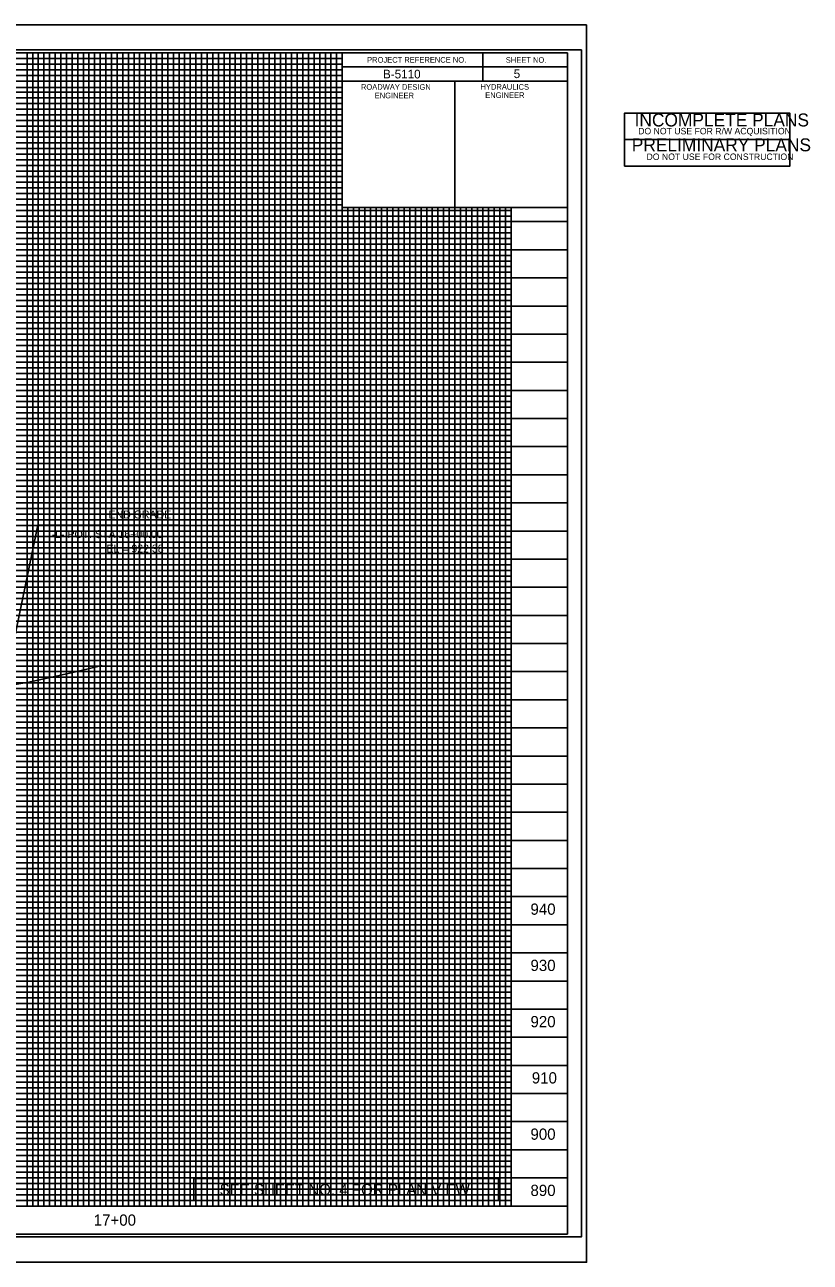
# Model space of a CAD drawing. Extents: x 573624 to 575507, y -53727 to -52273.
# Drawn here: x 574809 to 575507, y -53373 to -52273 of the extents above; entities that cross this region are included whole.
import ezdxf

# ---------------------------------------------------------------- set-up
doc = ezdxf.new("R2010")
doc.units = 0
for name, color, linetype in [('Exist Profile Cell', 7, 'Continuous'), ('Exist Vertical Profile Ground Line', 7, 'Continuous'), ('Exist Vertical Profile Horizontal Axis Label Major', 7, 'Continuous'), ('Exist Vertical Profile Vertical Axis Label', 7, 'Continuous'), ('Prop DSN Text', 7, 'Continuous'), ('Prop Grid Mask', 7, 'Continuous'), ('Prop VPI Label', 7, 'Continuous'), ('Sheet Cutting Line CELL', 7, 'Continuous'), ('Sheet Data Field CELL', 7, 'Continuous'), ('Sheet DOT Grid CELL', 7, 'Continuous'), ('Sheet Layout Profile Border', 7, 'Continuous'), ('Sheet Plot Border Inside CELL', 7, 'Continuous'), ('Sheet Plot Border Outside CELL', 7, 'Continuous'), ('Sheet Profile CELL', 7, 'Continuous'), ('Sheet Profile Grid Major CELL', 7, 'Continuous'), ('Sheet Profile Grid Middle CELL', 7, 'Continuous'), ('Sheet Profile Grid Minor CELL', 7, 'Continuous'), ('Sheet Sticker Incomplete CELL', 7, 'Continuous'), ('Sheet Sticker Preliminary CELL', 7, 'Continuous')]:
    doc.layers.add(name, color=color, linetype=linetype)

msp = doc.modelspace()

# ---------------------------------------------------------------- linework, layer by layer
at = {"layer": 'Exist Profile Cell'}
msp.add_line((574190.8, -53023.1), (574877.6, -53023.1), dxfattribs=at)
at = {"layer": 'Exist Vertical Profile Ground Line'}
for p, q in [((574855.3, -52847.9), (574877.3, -52842.6)), ((574877.3, -52842.6), (574877.6, -52842.4)), ((574810.8, -52857.7), (574838, -52851.7)), ((574838, -52851.7), (574840.5, -52851.2)), ((574840.5, -52851.2), (574855.3, -52847.9)), ((574794.9, -52860.5), (574810.5, -52857.8)), ((574810.5, -52857.8), (574810.8, -52857.7))]:
    msp.add_line(p, q, dxfattribs=at)
at = {"layer": 'Prop Grid Mask'}
msp.add_lwpolyline([(574959, -53318.2), (575229.5, -53318.2), (575229.5, -53298.5), (574959, -53298.5)], close=True, dxfattribs=at)
at = {"layer": 'Prop VPI Label'}
for p, q in [((574790.8, -52861.2), (574820.4, -52717.8)), ((574820.4, -52717.8), (574945.3, -52717.8))]:
    msp.add_line(p, q, dxfattribs=at)
at = {"layer": 'Sheet Cutting Line CELL'}
for p, q in [((575307.8, -52273.1), (573623.8, -52273.1)), ((573623.8, -53373.1), (575307.8, -53373.1))]:
    msp.add_line(p, q, dxfattribs=at)
at = {"layer": 'Sheet DOT Grid CELL'}
for p, q in [((574840.8, -52298.1), (574840.8, -53323.1)), ((574890.8, -52298.1), (574890.8, -53323.1)), ((574940.8, -52298.1), (574940.8, -53323.1)), ((574990.8, -52298.1), (574990.8, -53323.1)), ((575040.8, -52298.1), (575040.8, -53323.1)), ((573790.8, -52323.1), (575090.7, -52323.1)), ((573790.8, -52373.1), (575090.7, -52373.1)), ((573790.8, -52423.1), (575090.7, -52423.1)), ((575090.8, -53323.1), (575090.8, -52435.6)), ((575140.8, -53323.1), (575140.8, -52435.6)), ((575190.8, -53323.1), (575190.8, -52435.6)), ((575240.8, -53323.1), (575240.8, -52435.6)), ((573790.8, -52473.1), (575290.8, -52473.1)), ((573790.8, -52523.1), (575290.8, -52523.1)), ((573790.8, -52573.1), (575290.8, -52573.1)), ((573790.8, -52623.1), (575290.8, -52623.1)), ((573790.8, -52673.1), (575290.8, -52673.1)), ((573790.8, -52723.1), (575290.8, -52723.1)), ((573790.8, -52773.1), (575290.8, -52773.1)), ((573790.8, -52823.1), (575290.8, -52823.1)), ((573790.8, -52873.1), (575290.8, -52873.1)), ((573790.8, -52923.1), (575290.8, -52923.1)), ((573790.8, -52973.1), (575290.8, -52973.1)), ((573790.8, -53023.1), (575290.8, -53023.1)), ((573790.8, -53073.1), (575290.8, -53073.1)), ((573790.8, -53123.1), (575290.8, -53123.1)), ((573790.8, -53173.1), (575290.8, -53173.1)), ((573790.8, -53223.1), (575290.8, -53223.1)), ((573790.8, -53273.1), (575290.8, -53273.1))]:
    msp.add_line(p, q, dxfattribs=at)
at = {"layer": 'Sheet Layout Profile Border'}
msp.add_lwpolyline([(573840.8, -52298.1), (573840.8, -53323.1), (575240.8, -53323.1), (575240.8, -52435.6), (575090.7, -52435.6), (575090.7, -52298.1)], close=True, dxfattribs=at)
at = {"layer": 'Sheet Plot Border Inside CELL'}
msp.add_lwpolyline([(575303.3, -52295.5), (573636.8, -52295.5), (573636.8, -53350.6), (575303.3, -53350.6)], close=True, dxfattribs=at)
at = {"layer": 'Sheet Plot Border Outside CELL'}
msp.add_lwpolyline([(575307.8, -52273.1), (573623.8, -52273.1), (573623.8, -53373.1), (575307.8, -53373.1)], close=True, dxfattribs=at)
at = {"layer": 'Sheet Profile CELL'}
for p, q in [((575215.8, -52298.1), (575215.8, -52323.1)), ((575090.7, -52310.6), (575290.8, -52310.6)), ((575190.8, -52323.1), (575190.8, -52435.6)), ((575290.8, -53323.1), (573790.8, -53323.1))]:
    msp.add_line(p, q, dxfattribs=at)
for points in [[(575290.8, -52298.1), (573790.8, -52298.1), (573790.8, -53348.1), (575290.8, -53348.1)], [(575090.7, -52298.1), (575290.8, -52298.1), (575290.8, -52323.1), (575090.7, -52323.1)], [(575090.7, -52323.1), (575190.8, -52323.1), (575190.8, -52435.6), (575090.7, -52435.6)], [(575190.8, -52323.1), (575290.8, -52323.1), (575290.8, -52435.6), (575190.8, -52435.6)]]:
    msp.add_lwpolyline(points, close=True, dxfattribs=at)
at = {"layer": 'Sheet Profile Grid Major CELL'}
for points in [[(574790.8, -52298.1), (574840.8, -52298.1), (574840.8, -53323.1), (574890.8, -53323.1), (574890.8, -52298.1), (574940.8, -52298.1), (574940.8, -53323.1), (574990.8, -53323.1), (574990.8, -52298.1), (575040.8, -52298.1), (575040.8, -53323.1), (575090.8, -53323.1), (575090.8, -52298.1), (575117.1, -52298.1)], [(575090.7, -52373.1), (573790.9, -52373.1), (573790.9, -52323.1), (575090.7, -52323.1)], [(575290.8, -52473.1), (573790.8, -52473.1), (573790.8, -52423.1), (575090.7, -52423.1)], [(575140.8, -52435.6), (575140.8, -53323.1), (575190.8, -53323.1), (575190.8, -52435.6)], [(575240.8, -52435.6), (575240.8, -53323.1), (575290.8, -53323.1)], [(575290.8, -52573.1), (573790.8, -52573.1), (573790.8, -52523.1), (575290.8, -52523.1)], [(575290.8, -52673.1), (573790.8, -52673.1), (573790.8, -52623.1), (575290.8, -52623.1)], [(575290.8, -52773.1), (573790.8, -52773.1), (573790.8, -52723.1), (575290.8, -52723.1)], [(575290.8, -52873.1), (573790.8, -52873.1), (573790.8, -52823.1), (575290.8, -52823.1)], [(575290.8, -52973.1), (573790.8, -52973.1), (573790.8, -52923.1), (575290.8, -52923.1)], [(575290.8, -53073.1), (573790.8, -53073.1), (573790.8, -53023.1), (575290.8, -53023.1)], [(575290.8, -53173.1), (573790.8, -53173.1), (573790.8, -53123.1), (575290.8, -53123.1)], [(575290.8, -53273.1), (573790.8, -53273.1), (573790.8, -53223.1), (575290.8, -53223.1)]]:
    msp.add_lwpolyline(points, dxfattribs=at)
at = {"layer": 'Sheet Profile Grid Middle CELL'}
for points in [[(574765.8, -52298.1), (574815.8, -52298.1), (574815.8, -53323.1), (574865.8, -53323.1), (574865.8, -52298.1), (574915.8, -52298.1), (574915.8, -53323.1), (574965.8, -53323.1), (574965.8, -52298.1), (575015.8, -52298.1), (575015.8, -53323.1), (575065.8, -53323.1), (575065.8, -52298.1)], [(573790.8, -52348.1), (575090.7, -52348.1)], [(575090.7, -52398.1), (573790.8, -52398.1), (573790.8, -52448.1), (575290.8, -52448.1)], [(575115.8, -52435.6), (575115.8, -53323.1), (575165.8, -53323.1), (575165.8, -52435.6)], [(575215.8, -52435.6), (575215.8, -53323.1)], [(575290.8, -52498.1), (573790.8, -52498.1), (573790.8, -52548.1), (575290.8, -52548.1)], [(575290.8, -52598.1), (573790.8, -52598.1), (573790.8, -52648.1), (575290.8, -52648.1)], [(575290.8, -52698.1), (573790.8, -52698.1), (573790.8, -52748.1), (575290.8, -52748.1)], [(575290.8, -52798.1), (573790.8, -52798.1), (573790.8, -52848.1), (575290.8, -52848.1)], [(575290.8, -52898.1), (573790.8, -52898.1), (573790.8, -52948.1), (575290.8, -52948.1)], [(575290.8, -52998.1), (573790.8, -52998.1), (573790.8, -53048.1), (575290.8, -53048.1)], [(575290.8, -53098.1), (573790.8, -53098.1), (573790.8, -53148.1), (575290.8, -53148.1)], [(575290.8, -53198.1), (573790.8, -53198.1), (573790.8, -53248.1), (575290.8, -53248.1)], [(575290.8, -53298.1), (573790.8, -53298.1)]]:
    msp.add_lwpolyline(points, dxfattribs=at)
at = {"layer": 'Sheet Profile Grid Minor CELL'}
for p, q in [((575240.8, -52478.1), (573840.8, -52478.1)), ((573840.8, -52483.1), (575240.8, -52483.1)), ((575240.8, -52503.1), (573840.8, -52503.1))]:
    msp.add_line(p, q, dxfattribs=at)
for points in [[(575090.7, -52303.1), (573840.8, -52303.1), (573840.8, -52308.1), (575090.7, -52308.1)], [(574805.8, -52298.1), (574810.8, -52298.1), (574810.8, -53323.1), (574820.8, -53323.1), (574820.8, -52298.1), (574825.8, -52298.1), (574825.8, -53323.1), (574830.8, -53323.1), (574830.8, -52298.1), (574835.8, -52298.1), (574835.8, -53323.1), (574845.8, -53323.1), (574845.8, -52298.1), (574850.8, -52298.1), (574850.8, -53323.1), (574855.8, -53323.1), (574855.8, -52298.1), (574860.8, -52298.1), (574860.8, -53323.1)], [(574860.8, -53323.1), (574870.8, -53323.1), (574870.8, -52298.1), (574875.8, -52298.1), (574875.8, -53323.1), (574880.8, -53323.1), (574880.8, -52298.1), (574885.8, -52298.1), (574885.8, -53323.1), (574895.8, -53323.1), (574895.8, -52298.1), (574900.8, -52298.1), (574900.8, -53323.1), (574905.8, -53323.1), (574905.8, -52298.1), (574910.8, -52298.1), (574910.8, -53323.1), (574920.8, -53323.1), (574920.8, -52298.1), (574925.8, -52298.1), (574925.8, -53323.1), (574930.8, -53323.1), (574930.8, -52298.1), (574935.8, -52298.1), (574935.8, -53323.1), (574945.8, -53323.1), (574945.8, -52298.1), (574950.8, -52298.1), (574950.8, -53323.1), (574955.8, -53323.1), (574955.8, -52298.1), (574960.8, -52298.1), (574960.8, -53323.1), (574970.8, -53323.1), (574970.8, -52298.1), (574975.8, -52298.1), (574975.8, -53323.1), (574980.8, -53323.1), (574980.8, -52298.1), (574985.8, -52298.1), (574985.8, -53323.1), (574995.8, -53323.1), (574995.8, -52298.1), (575000.8, -52298.1), (575000.8, -53323.1), (575005.8, -53323.1), (575005.8, -52298.1), (575010.8, -52298.1), (575010.8, -53323.1), (575020.8, -53323.1), (575020.8, -52298.1), (575025.8, -52298.1), (575025.8, -53323.1), (575030.8, -53323.1), (575030.8, -52298.1), (575035.8, -52298.1), (575035.8, -53323.1), (575045.8, -53323.1), (575045.8, -52298.1), (575050.8, -52298.1), (575050.8, -53323.1), (575055.8, -53323.1), (575055.8, -52298.1), (575060.8, -52298.1), (575060.8, -53323.1), (575070.8, -53323.1), (575070.8, -52298.1), (575075.8, -52298.1), (575075.8, -53323.1), (575080.8, -53323.1), (575080.8, -52298.1), (575085.8, -52298.1), (575085.8, -53323.1), (575095.8, -53323.1), (575095.8, -52435.6)], [(575090.7, -52313.1), (573840.8, -52313.1), (573840.8, -52318.1), (575090.7, -52318.1)], [(575090.7, -52328.8), (573841.8, -52328.8), (573841.8, -52333.1), (575090.7, -52333.1)], [(575090.7, -52338.1), (573840.8, -52338.1), (573840.8, -52343.1), (575090.7, -52343.1)], [(575090.7, -52353.1), (573840.8, -52353.1), (573840.8, -52358.1), (575090.7, -52358.1)], [(575090.7, -52363.1), (573840.8, -52363.1), (573840.8, -52368.1), (575090.7, -52368.1)], [(575090.7, -52378.1), (573840.8, -52378.1), (573840.8, -52383.1), (575090.7, -52383.1)], [(575090.7, -52388.1), (573840.8, -52388.1), (573840.8, -52393.1), (575090.7, -52393.1)], [(575090.7, -52403.1), (573840.8, -52403.1), (573840.8, -52408.1), (575090.7, -52408.1)], [(575090.7, -52413.1), (573840.8, -52413.1), (573840.8, -52418.1), (575090.7, -52418.1)], [(575090.7, -52428.1), (573840.8, -52428.1), (573840.8, -52433.1), (575090.7, -52433.1)], [(575100.8, -52435.6), (575100.8, -53323.1), (575105.8, -53323.1), (575105.8, -52435.6)], [(575110.8, -52435.6), (575110.8, -53323.1), (575120.8, -53323.1), (575120.8, -52435.6)], [(575125.8, -52435.6), (575125.8, -53323.1), (575130.8, -53323.1), (575130.8, -52435.6)], [(575135.8, -52435.6), (575135.8, -53323.1), (575145.8, -53323.1), (575145.8, -52435.6)], [(575150.8, -52435.6), (575150.8, -53323.1), (575155.8, -53323.1), (575155.8, -52435.6)], [(575160.8, -52435.6), (575160.8, -53323.1), (575170.8, -53323.1), (575170.8, -52435.6)], [(575175.8, -52435.6), (575175.8, -53323.1)], [(575175.8, -53323.1), (575180.8, -53323.1), (575180.8, -52435.6)], [(575185.8, -52435.6), (575185.8, -53323.1), (575195.8, -53323.1), (575195.8, -52435.6)], [(575200.8, -52435.6), (575200.8, -53323.1), (575205.8, -53323.1), (575205.8, -52435.6)], [(575210.8, -52435.6), (575210.8, -53323.1), (575220.8, -53323.1), (575220.8, -52435.6)], [(575225.8, -52435.6), (575225.8, -53323.1), (575230.8, -53323.1), (575230.8, -52435.6)], [(575235.8, -52435.6), (575235.8, -53323.1), (575245.8, -53323.1)], [(575240.8, -52438.1), (573840.8, -52438.1), (573840.8, -52438.1), (573840.8, -52458.1), (575240.8, -52458.1)], [(573840.8, -52443.1), (575240.8, -52443.1)], [(575240.8, -52453.1), (573840.8, -52453.1)], [(575240.8, -52463.1), (573840.8, -52463.1), (573840.8, -52468.1), (575240.8, -52468.1)], [(575240.8, -52488.1), (573840.8, -52488.1), (573840.8, -52493.1), (575240.8, -52493.1)], [(575240.8, -52508.1), (573840.8, -52508.1), (573840.8, -52513.1), (575240.8, -52513.1)], [(575240.8, -52518.1), (573840.8, -52518.1)], [(573840.8, -52528.1), (575240.8, -52528.1)], [(575240.8, -52533.1), (573840.8, -52533.1), (573840.8, -52538.1), (575240.8, -52538.1)], [(575240.8, -52543.1), (573840.8, -52543.1), (573840.8, -52553.1), (575240.8, -52553.1)], [(575240.8, -52558.1), (573840.8, -52558.1), (573840.8, -52563.1), (575240.8, -52563.1)], [(575240.8, -52568.1), (573840.8, -52568.1), (573840.8, -52578.1), (575240.8, -52578.1)], [(575240.8, -52583.1), (573840.8, -52583.1), (573840.8, -52588.1), (575240.8, -52588.1)], [(575240.8, -52593.1), (573840.8, -52593.1), (573840.8, -52603.1), (575240.8, -52603.1)], [(575240.8, -52608.1), (573840.8, -52608.1), (573840.8, -52613.1), (575240.8, -52613.1)], [(575240.8, -52618.1), (573840.8, -52618.1), (573840.8, -52628.1), (575240.8, -52628.1)], [(575240.8, -52633.1), (573840.8, -52633.1), (573840.8, -52638.1), (575240.8, -52638.1)], [(575240.8, -52643.1), (573840.8, -52643.1), (573840.8, -52653.1), (575240.8, -52653.1)], [(575240.8, -52658.1), (573840.8, -52658.1), (573840.8, -52663.1), (575240.8, -52663.1)], [(575240.8, -52668.1), (573840.8, -52668.1), (573840.8, -52678.1), (575240.8, -52678.1)], [(575240.8, -52683.1), (573840.8, -52683.1), (573840.8, -52688.1), (575240.8, -52688.1)], [(575240.8, -52693.1), (573840.8, -52693.1), (573840.8, -52703.1), (575240.8, -52703.1)], [(575240.8, -52708.1), (573840.8, -52708.1), (573840.8, -52713.1), (575240.8, -52713.1)], [(575240.8, -52718.1), (573840.8, -52718.1), (573840.8, -52728.1), (575240.8, -52728.1)], [(575240.8, -52733.1), (573840.8, -52733.1), (573840.8, -52738.1), (575240.8, -52738.1)], [(575240.8, -52743.1), (573840.8, -52743.1), (573840.8, -52753.1), (575240.8, -52753.1)], [(575240.8, -52758.1), (573840.8, -52758.1), (573840.8, -52763.1), (575240.8, -52763.1)], [(575240.8, -52768.1), (573840.8, -52768.1), (573840.8, -52778.1), (575240.8, -52778.1)], [(575240.8, -52783.1), (573840.8, -52783.1), (573840.8, -52788.1), (575240.8, -52788.1)], [(575240.8, -52793.1), (573840.8, -52793.1), (573840.8, -52803.1), (575240.8, -52803.1)], [(575240.8, -52808.1), (573840.8, -52808.1), (573840.8, -52813.1), (575240.8, -52813.1)], [(575240.8, -52818.1), (573840.8, -52818.1)], [(573840.8, -52828.1), (575240.8, -52828.1)], [(575240.8, -52833.1), (573840.8, -52833.1), (573840.8, -52838.1), (575240.8, -52838.1)], [(575240.8, -52843.1), (573840.8, -52843.1), (573840.8, -52853.1), (575240.8, -52853.1)], [(575240.8, -52858.1), (573840.8, -52858.1), (573840.8, -52863.1), (575240.8, -52863.1)], [(575240.8, -52868.1), (573840.8, -52868.1), (573840.8, -52878.1), (575240.8, -52878.1)], [(575240.8, -52883.1), (573840.8, -52883.1), (573840.8, -52888.1), (575240.8, -52888.1)], [(575240.8, -52893.1), (573840.8, -52893.1), (573840.8, -52903.1), (575240.8, -52903.1)], [(575240.8, -52908.1), (573840.8, -52908.1), (573840.8, -52913.1), (575240.8, -52913.1)], [(575240.8, -52918.1), (573840.8, -52918.1), (573840.8, -52928.1), (575240.8, -52928.1)], [(575240.8, -52933.1), (573840.8, -52933.1), (573840.8, -52938.1), (575240.8, -52938.1)], [(575240.8, -52943.1), (573840.8, -52943.1), (573840.8, -52953.1), (575240.8, -52953.1)], [(575240.8, -52958.1), (573840.8, -52958.1), (573840.8, -52963.1), (575240.8, -52963.1)], [(575240.8, -52968.1), (573840.8, -52968.1), (573840.8, -52978.1), (575240.8, -52978.1)], [(575240.8, -52983.1), (573840.8, -52983.1), (573840.8, -52988.1), (575240.8, -52988.1)], [(575240.8, -52993.1), (573840.8, -52993.1), (573840.8, -53003.1), (575240.8, -53003.1)], [(575240.8, -53008.1), (573840.8, -53008.1), (573840.8, -53013.1), (575240.8, -53013.1)], [(575240.8, -53018.1), (573840.8, -53018.1), (573840.8, -53028.1), (575240.8, -53028.1)], [(575240.8, -53033.1), (573840.8, -53033.1), (573840.8, -53038.1), (575240.8, -53038.1)], [(575240.8, -53043.1), (573840.8, -53043.1), (573840.8, -53053.1), (575240.8, -53053.1)], [(575240.8, -53058.1), (573840.8, -53058.1), (573840.8, -53063.1), (575240.8, -53063.1)], [(575240.8, -53068.1), (573840.8, -53068.1), (573840.8, -53078.1), (575240.8, -53078.1)], [(575240.8, -53083.1), (573840.8, -53083.1), (573840.8, -53088.1), (575240.8, -53088.1)], [(575240.8, -53093.1), (573840.8, -53093.1), (573840.8, -53103.1), (575240.8, -53103.1)], [(575240.8, -53108.1), (573840.8, -53108.1), (573840.8, -53113.1), (575240.8, -53113.1)], [(575240.8, -53118.1), (573840.8, -53118.1)], [(573840.8, -53128.1), (575240.8, -53128.1)], [(575240.8, -53133.1), (573840.8, -53133.1), (573840.8, -53138.1), (575240.8, -53138.1)], [(575240.8, -53143.1), (573840.8, -53143.1)], [(573840.8, -53153.1), (575240.8, -53153.1)], [(575240.8, -53158.1), (573840.8, -53158.1), (573840.8, -53163.1), (575240.8, -53163.1)], [(575240.8, -53168.1), (573840.8, -53168.1), (573840.8, -53178.1), (575240.8, -53178.1)], [(575240.8, -53183.1), (573840.8, -53183.1), (573840.8, -53188.1), (575240.8, -53188.1)], [(575240.8, -53193.1), (573840.8, -53193.1), (573840.8, -53203.1), (575240.8, -53203.1)], [(575240.8, -53208.1), (573840.8, -53208.1), (573840.8, -53213.1), (575240.8, -53213.1)], [(575240.8, -53218.1), (573840.8, -53218.1), (573840.8, -53228.1), (575240.8, -53228.1)], [(575240.8, -53233.1), (573840.8, -53233.1), (573840.8, -53238.1), (575240.8, -53238.1)], [(575240.8, -53243.1), (573840.8, -53243.1), (573840.8, -53253.1), (575240.8, -53253.1)], [(575240.8, -53258.1), (573840.8, -53258.1), (573840.8, -53263.1), (575240.8, -53263.1)], [(575240.8, -53268.1), (573840.8, -53268.1), (573840.8, -53278.1), (575240.8, -53278.1)], [(575240.8, -53283.1), (573840.8, -53283.1), (573840.8, -53288.1), (575240.8, -53288.1)], [(575240.8, -53293.1), (573840.8, -53293.1), (573840.8, -53303.1), (575240.8, -53303.1)], [(575240.8, -53308.1), (573840.8, -53308.1), (573840.8, -53313.1), (575240.8, -53313.1)], [(575240.8, -53318.1), (573840.8, -53318.1)]]:
    msp.add_lwpolyline(points, dxfattribs=at)
at = {"layer": 'Sheet Sticker Incomplete CELL'}
msp.add_lwpolyline([(575341.5, -52375.2), (575341.5, -52351.7), (575488.5, -52351.7), (575488.5, -52375.2)], close=True, dxfattribs=at)
at = {"layer": 'Sheet Sticker Preliminary CELL'}
msp.add_lwpolyline([(575341.5, -52398.7), (575341.5, -52375.2), (575488.5, -52375.2), (575488.5, -52398.7)], close=True, dxfattribs=at)

# ---------------------------------------------------------------- texts
at = {"layer": 'Exist Vertical Profile Horizontal Axis Label Major'}
msp.add_text('17+00', height=10, dxfattribs=at).set_placement((574870, -53340.6))
at = {"layer": 'Exist Vertical Profile Vertical Axis Label'}
for s, p in [('940', (575258, -53064.2)), ('930', (575258, -53114.2)), ('920', (575258, -53164.2)), ('910', (575259.2, -53214.2)), ('900', (575258, -53264.2)), ('890', (575258, -53314.2))]:
    msp.add_text(s, height=10, dxfattribs=at).set_placement(p)
at = {"layer": 'Prop DSN Text'}
msp.add_text('SEE SHEET NO. 4 FOR PLAN VIEW', height=10, dxfattribs=at).set_placement((574981.9, -53313.5))
at = {"layer": 'Prop VPI Label'}
for s, p in [('END GRADE', (574883.2, -52711.9)), ('-L- POT. STA 16+00.00', (574832.7, -52729.4)), ('EL = 922.38', (574881.4, -52742.2))]:
    msp.add_text(s, height=7, dxfattribs=at).set_placement(p)
at = {"layer": 'Sheet Data Field CELL'}
for s, p in [('B-5110   ', (575127, -52320.8)), ('5  ', (575243.1, -52320.5))]:
    msp.add_text(s, height=7.75, dxfattribs=at).set_placement(p)
at = {"layer": 'Sheet Profile CELL'}
for s, p in [('PROJECT REFERENCE NO.', (575112.9, -52306.8)), ('SHEET NO.', (575236.1, -52306.9)), ('ROADWAY DESIGN', (575107.4, -52330.9)), ('HYDRAULICS', (575213.6, -52330.8)), ('ENGINEER', (575119.6, -52338.5)), ('ENGINEER', (575217.8, -52338.2))]:
    msp.add_text(s, height=5, dxfattribs=at).set_placement(p)
at = {"layer": 'Sheet Sticker Incomplete CELL'}
for s, height, p in [('INCOMPLETE PLANS', 11.52, (575350.5, -52363.5)), ('DO NOT USE FOR R/W ACQUISITION', 5.76, (575353.7, -52370.5))]:
    msp.add_text(s, height=height, dxfattribs=at).set_placement(p)
at = {"layer": 'Sheet Sticker Preliminary CELL'}
for s, height, p in [('PRELIMINARY PLANS', 11.52, (575348, -52385.6)), ('DO NOT USE FOR CONSTRUCTION', 5.76, (575361.1, -52393.3))]:
    msp.add_text(s, height=height, dxfattribs=at).set_placement(p)

doc.saveas('drawing.dxf')
